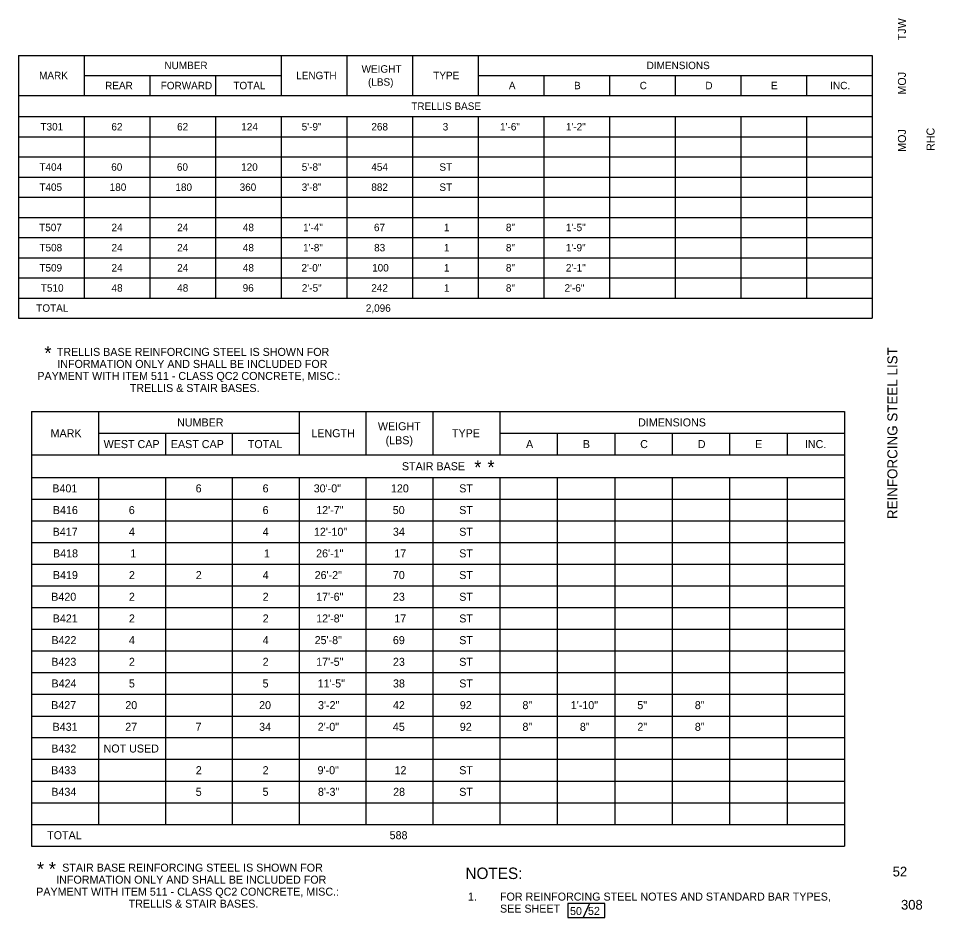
# Model space of a CAD drawing. Extents: x -47.5 to 51.5, y 0.9 to 23.7.
# Drawn here: x 17.38 to 33.41, y 0.94 to 16.66 of the extents above; entities that cross this region are included whole.
import ezdxf

# ---------------------------------------------------------------- set-up
doc = ezdxf.new("R2010")
doc.units = 0
for name, color, linetype in [('BR_P_Gen_Text', 7, 'Continuous'), ('BR_X_Slab_Const_Joint', 7, 'Continuous'), ('BR_X_Slab_Object', 7, 'Continuous')]:
    doc.layers.add(name, color=color, linetype=linetype)

msp = doc.modelspace()

# ---------------------------------------------------------------- linework, layer by layer
at = {"layer": 'BR_X_Slab_Const_Joint'}
msp.add_line((27.372, 1.195), (27.257, 0.945), dxfattribs=at)
msp.add_lwpolyline([(26.99, 0.945), (27.64, 0.945), (27.64, 1.195), (26.99, 1.195)], close=True, dxfattribs=at)
at = {"layer": 'BR_X_Slab_Object'}
for p, q in [((17.385, 16.015), (32.314, 16.015)), ((17.385, 16.015), (17.385, 11.422)), ((18.533, 16.015), (18.533, 15.311)), ((21.978, 16.015), (21.978, 15.311)), ((23.127, 16.015), (23.127, 15.311)), ((24.275, 16.015), (24.275, 15.311)), ((25.424, 16.015), (25.424, 15.311)), ((32.314, 16.015), (32.314, 11.422)), ((18.533, 15.663), (21.978, 15.663)), ((19.681, 15.663), (19.681, 15.311)), ((20.83, 15.663), (20.83, 15.311)), ((25.424, 15.663), (32.314, 15.663)), ((26.572, 15.663), (26.572, 15.311)), ((27.72, 15.663), (27.72, 15.311)), ((28.869, 15.663), (28.869, 15.311)), ((30.017, 15.663), (30.017, 15.311)), ((31.166, 15.663), (31.166, 15.311)), ((17.385, 15.311), (32.314, 15.311)), ((17.385, 14.944), (32.314, 14.944)), ((18.533, 14.944), (18.533, 11.774)), ((19.681, 14.944), (19.681, 11.774)), ((20.83, 14.944), (20.83, 11.774)), ((21.978, 14.944), (21.978, 11.774)), ((23.127, 14.944), (23.127, 11.774)), ((24.275, 14.944), (24.275, 11.774)), ((25.424, 14.944), (25.424, 11.774)), ((26.572, 14.944), (26.572, 11.774)), ((27.72, 14.944), (27.72, 11.774)), ((28.869, 14.944), (28.869, 11.774)), ((30.017, 14.944), (30.017, 11.774)), ((31.166, 14.944), (31.166, 11.774)), ((17.385, 14.591), (32.314, 14.591)), ((17.385, 14.239), (32.314, 14.239)), ((17.385, 13.887), (32.314, 13.887)), ((17.385, 13.535), (32.314, 13.535)), ((17.385, 13.183), (32.314, 13.183)), ((17.385, 12.831), (32.314, 12.831)), ((17.385, 12.478), (32.314, 12.478)), ((17.385, 12.126), (32.314, 12.126)), ((17.385, 11.774), (32.314, 11.774)), ((17.385, 11.422), (32.314, 11.422)), ((17.616, 9.789), (31.83, 9.789)), ((17.616, 9.789), (17.616, 2.196)), ((18.785, 9.789), (18.785, 9.032)), ((22.294, 9.789), (22.294, 9.032)), ((23.463, 9.789), (23.463, 9.032)), ((24.632, 9.789), (24.632, 9.032)), ((25.802, 9.789), (25.802, 9.032)), ((31.83, 9.789), (31.83, 2.196)), ((18.785, 9.411), (22.294, 9.411)), ((19.955, 9.411), (19.955, 9.032)), ((21.124, 9.411), (21.124, 9.032)), ((25.802, 9.411), (31.83, 9.411)), ((26.806, 9.411), (26.806, 9.032)), ((27.811, 9.411), (27.811, 9.032)), ((28.816, 9.411), (28.816, 9.032)), ((29.821, 9.411), (29.821, 9.032)), ((30.825, 9.411), (30.825, 9.032)), ((17.616, 9.032), (31.83, 9.032)), ((17.616, 8.636), (31.83, 8.636)), ((18.785, 8.636), (18.785, 2.575)), ((19.955, 8.636), (19.955, 2.575)), ((21.124, 8.636), (21.124, 2.575)), ((22.294, 8.636), (22.294, 2.575)), ((23.463, 8.636), (23.463, 2.575)), ((24.632, 8.636), (24.632, 2.575)), ((25.802, 8.636), (25.802, 2.575)), ((26.806, 8.636), (26.806, 2.575)), ((27.811, 8.636), (27.811, 2.575)), ((28.816, 8.636), (28.816, 2.575)), ((29.821, 8.636), (29.821, 2.575)), ((30.825, 8.636), (30.825, 2.575)), ((17.616, 8.258), (31.83, 8.258)), ((17.616, 7.879), (31.83, 7.879)), ((17.616, 7.5), (31.83, 7.5)), ((17.616, 7.121), (31.83, 7.121)), ((17.616, 6.742), (31.83, 6.742)), ((17.616, 6.364), (31.83, 6.364)), ((17.616, 5.985), (31.83, 5.985)), ((17.616, 5.606), (31.83, 5.606)), ((17.616, 5.227), (31.83, 5.227)), ((17.616, 4.848), (31.83, 4.848)), ((17.616, 4.469), (31.83, 4.469)), ((17.616, 4.091), (31.83, 4.091)), ((17.616, 3.712), (31.83, 3.712)), ((17.616, 3.333), (31.83, 3.333)), ((17.616, 2.954), (31.83, 2.954)), ((17.616, 2.575), (31.83, 2.575)), ((17.616, 2.196), (31.83, 2.196))]:
    msp.add_line(p, q, dxfattribs=at)

# ---------------------------------------------------------------- texts
at = {"layer": 'BR_P_Gen_Text'}
for s, height, p in [('NUMBER', 0.1302, (19.939, 15.774)), ('DIMENSIONS', 0.1302, (28.37, 15.774)), ('MARK', 0.1302, (17.748, 15.598)), ('LENGTH', 0.1302, (22.243, 15.598)), ('WEIGHT', 0.1302, (23.386, 15.712)), ('TYPE', 0.1302, (24.639, 15.598)), ('REAR', 0.1302, (18.902, 15.422)), ('FORWARD', 0.1302, (19.874, 15.422)), ('TOTAL', 0.1302, (21.144, 15.422)), ('(LBS)', 0.1302, (23.498, 15.484)), ('A', 0.13, (25.961, 15.422)), ('B', 0.13, (27.101, 15.422)), ('C', 0.13, (28.248, 15.422)), ('D', 0.13, (29.397, 15.422)), ('E', 0.13, (30.544, 15.422)), ('INC.', 0.1302, (31.579, 15.422)), ('TRELLIS BASE', 0.13015, (24.255, 15.062)), ('T301', 0.1302, (17.772, 14.702)), ('62', 0.1302, (19.012, 14.702)), ('62', 0.1302, (20.16, 14.702)), ('124', 0.1302, (21.283, 14.702)), ('5\'-9"', 0.1302, (22.339, 14.702)), ('268', 0.1302, (23.557, 14.702)), ('3', 0.13, (24.804, 14.702)), ('1\'-6"', 0.1302, (25.807, 14.702)), ('1\'-2"', 0.1302, (26.958, 14.702)), ('T404', 0.1302, (17.753, 13.998)), ('60', 0.1302, (19.009, 13.998)), ('60', 0.1302, (20.157, 13.998)), ('120', 0.1302, (21.28, 13.998)), ('5\'-8"', 0.1302, (22.34, 13.998)), ('454', 0.1302, (23.556, 13.998)), ('ST', 0.1302, (24.746, 13.998)), ('T405', 0.1302, (17.752, 13.646)), ('180', 0.1302, (18.982, 13.646)), ('180', 0.1302, (20.131, 13.646)), ('360', 0.1302, (21.254, 13.646)), ('3\'-8"', 0.1302, (22.339, 13.646)), ('882', 0.1302, (23.556, 13.646)), ('ST', 0.1302, (24.746, 13.646)), ('T507', 0.1302, (17.749, 12.942)), ('24', 0.1302, (19.014, 12.942)), ('24', 0.1302, (20.162, 12.942)), ('48', 0.1302, (21.31, 12.942)), ('1\'-4"', 0.1302, (22.363, 12.942)), ('67', 0.1302, (23.602, 12.942)), ('1', 0.13, (24.825, 12.942)), ('8"', 0.1302, (25.909, 12.942)), ('1\'-5"', 0.1302, (26.957, 12.942)), ('T508', 0.1302, (17.754, 12.589)), ('24', 0.1302, (19.014, 12.589)), ('24', 0.1302, (20.162, 12.589)), ('48', 0.1302, (21.31, 12.589)), ('1\'-8"', 0.1302, (22.363, 12.589)), ('83', 0.1302, (23.605, 12.589)), ('1', 0.13, (24.825, 12.589)), ('8"', 0.1302, (25.909, 12.589)), ('1\'-9"', 0.1302, (26.956, 12.589)), ('T509', 0.1302, (17.753, 12.237)), ('24', 0.1302, (19.014, 12.237)), ('24', 0.1302, (20.162, 12.237)), ('48', 0.1302, (21.31, 12.237)), ('2\'-0"', 0.1302, (22.335, 12.237)), ('100', 0.1302, (23.57, 12.237)), ('1', 0.13, (24.825, 12.237)), ('8"', 0.1302, (25.909, 12.237)), ('2\'-1"', 0.1302, (26.958, 12.237)), ('T510', 0.1302, (17.779, 11.885)), ('48', 0.1302, (19.014, 11.885)), ('48', 0.1302, (20.162, 11.885)), ('96', 0.1302, (21.307, 11.885)), ('2\'-5"', 0.1302, (22.341, 11.885)), ('242', 0.1302, (23.556, 11.885)), ('8"', 0.1302, (25.909, 11.885)), ('2\'-6"', 0.1302, (26.934, 11.885)), ('1', 0.13, (24.825, 11.885)), ('TOTAL', 0.1302, (17.698, 11.533)), ('2,096', 0.1302, (23.46, 11.533)), ('NUMBER', 0.14, (20.161, 9.53)), ('DIMENSIONS', 0.14, (28.22, 9.53)), ('MARK', 0.14, (17.949, 9.341)), ('LENGTH', 0.14, (22.508, 9.341)), ('WEIGHT', 0.14, (23.671, 9.463)), ('TYPE', 0.14, (24.966, 9.341)), ('WEST CAP', 0.14, (18.876, 9.151)), ('EAST CAP', 0.14, (20.051, 9.151)), ('TOTAL', 0.14, (21.397, 9.151)), ('(LBS)', 0.14, (23.806, 9.218)), ('C', 0.14, (28.257, 9.151)), ('INC.', 0.14, (31.136, 9.151)), ('A', 0.14, (26.261, 9.151)), ('B', 0.14, (27.254, 9.151)), ('D', 0.14, (29.264, 9.151)), ('E', 0.14, (30.266, 9.151)), ('STAIR BASE ', 0.14, (24.091, 8.764)), ('B401', 0.14, (17.979, 8.377)), ('6', 0.14, (20.485, 8.377)), ('6', 0.14, (21.655, 8.377)), ('30\'-0"', 0.14, (22.549, 8.377)), ('120', 0.14, (23.899, 8.377)), ('ST', 0.14, (25.093, 8.377)), ('B416', 0.14, (17.988, 7.998)), ('6', 0.14, (19.316, 7.998)), ('6', 0.14, (21.655, 7.998)), ('12\'-7"', 0.14, (22.593, 7.998)), ('50', 0.14, (23.931, 7.998)), ('ST', 0.14, (25.093, 7.998)), ('B417', 0.14, (17.985, 7.619)), ('4', 0.14, (19.318, 7.619)), ('4', 0.14, (21.657, 7.619)), ('12\'-10"', 0.14, (22.553, 7.619)), ('34', 0.14, (23.934, 7.619)), ('ST', 0.14, (25.093, 7.619)), ('B418', 0.14, (17.991, 7.241)), ('1', 0.14, (19.341, 7.241)), ('1', 0.14, (21.68, 7.241)), ('26\'-1"', 0.14, (22.591, 7.241)), ('17', 0.14, (23.958, 7.241)), ('ST', 0.14, (25.093, 7.241)), ('B419', 0.14, (17.989, 6.862)), ('2', 0.14, (19.318, 6.862)), ('2', 0.14, (20.487, 6.862)), ('4', 0.14, (21.657, 6.862)), ('26\'-2"', 0.14, (22.565, 6.862)), ('70', 0.14, (23.932, 6.862)), ('ST', 0.14, (25.093, 6.862)), ('B420', 0.14, (17.96, 6.483)), ('2', 0.14, (19.318, 6.483)), ('2', 0.14, (21.656, 6.483)), ('17\'-6"', 0.14, (22.591, 6.483)), ('23', 0.14, (23.934, 6.483)), ('ST', 0.14, (25.093, 6.483)), ('B421', 0.14, (17.986, 6.104)), ('2', 0.14, (19.318, 6.104)), ('2', 0.14, (21.656, 6.104)), ('12\'-8"', 0.14, (22.592, 6.104)), ('17', 0.14, (23.958, 6.104)), ('ST', 0.14, (25.093, 6.104)), ('B422', 0.14, (17.963, 5.725)), ('4', 0.14, (19.318, 5.725)), ('4', 0.14, (21.657, 5.725)), ('25\'-8"', 0.14, (22.565, 5.725)), ('69', 0.14, (23.933, 5.725)), ('ST', 0.14, (25.093, 5.725)), ('B423', 0.14, (17.961, 5.346)), ('2', 0.14, (19.318, 5.346)), ('2', 0.14, (21.656, 5.346)), ('17\'-5"', 0.14, (22.592, 5.346)), ('23', 0.14, (23.934, 5.346)), ('ST', 0.14, (25.093, 5.346)), ('B424', 0.14, (17.964, 4.968)), ('5', 0.14, (19.317, 4.968)), ('5', 0.14, (21.655, 4.968)), ('11\'-5"', 0.14, (22.619, 4.968)), ('38', 0.14, (23.935, 4.968)), ('ST', 0.14, (25.093, 4.968)), ('B427', 0.14, (17.959, 4.589)), ('20', 0.14, (19.255, 4.589)), ('20', 0.14, (21.594, 4.589)), ('3\'-2"', 0.14, (22.624, 4.589)), ('42', 0.14, (23.934, 4.589)), ('92', 0.14, (25.103, 4.589)), ('8"', 0.14, (26.198, 4.589)), ('1\'-10"', 0.14, (27.043, 4.589)), ('5"', 0.14, (28.207, 4.589)), ('8"', 0.14, (29.212, 4.589)), ('B431', 0.14, (17.984, 4.21)), ('27', 0.14, (19.254, 4.21)), ('7', 0.14, (20.483, 4.21)), ('34', 0.14, (21.595, 4.21)), ('2\'-0"', 0.14, (22.619, 4.21)), ('45', 0.14, (23.933, 4.21)), ('92', 0.14, (25.103, 4.21)), ('8"', 0.14, (26.198, 4.21)), ('8"', 0.14, (27.202, 4.21)), ('2"', 0.14, (28.208, 4.21)), ('8"', 0.14, (29.212, 4.21)), ('B432', 0.14, (17.961, 3.831)), ('NOT USED', 0.14, (18.875, 3.831)), ('B433', 0.14, (17.959, 3.452)), ('2', 0.14, (20.487, 3.452)), ('2', 0.14, (21.656, 3.452)), ('9\'-0"', 0.14, (22.616, 3.452)), ('12', 0.14, (23.962, 3.452)), ('ST', 0.14, (25.093, 3.452)), ('B434', 0.14, (17.961, 3.074)), ('5', 0.14, (20.486, 3.074)), ('5', 0.14, (21.655, 3.074)), ('8\'-3"', 0.14, (22.623, 3.074)), ('28', 0.14, (23.937, 3.074)), ('ST', 0.14, (25.093, 3.074)), ('TOTAL', 0.14, (17.889, 2.316)), ('588', 0.14, (23.876, 2.316)), ('52', 0.17, (32.671, 1.665)), ('50', 0.14, (27.03, 0.991)), ('52', 0.14, (27.344, 0.993)), ('308', 0.17, (32.817, 1.085))]:
    msp.add_text(s, height=height, dxfattribs=at).set_placement(p)
at = {"layer": 'BR_X_Slab_Const_Joint'}
for s, height, p in [('*', 0.24, (17.84, 10.692)), ('TRELLIS BASE REINFORCING STEEL IS SHOWN FOR', 0.14, (18.057, 10.762)), ('INFORMATION ONLY AND SHALL BE INCLUDED FOR ', 0.14, (18.066, 10.552)), ('PAYMENT WITH ITEM 511 - CLASS QC2 CONCRETE, MISC.:', 0.14, (17.717, 10.342)), ('TRELLIS & STAIR BASES.', 0.14, (19.333, 10.132)), ('*', 0.24, (25.355, 8.696)), ('*', 0.24, (25.586, 8.696)), ('*', 0.24, (17.71, 1.676)), ('*', 0.24, (17.917, 1.676)), ('STAIR BASE REINFORCING STEEL IS SHOWN FOR ', 0.14, (18.152, 1.749)), ('NOTES:', 0.2, (25.202, 1.62)), ('INFORMATION ONLY AND SHALL BE INCLUDED FOR ', 0.14, (18.047, 1.539)), ('PAYMENT WITH ITEM 511 - CLASS QC2 CONCRETE, MISC.:', 0.14, (17.697, 1.329)), ('1.', 0.14, (25.246, 1.243)), ('1.', 0.14, (25.246, 1.243)), ('FOR REINFORCING STEEL NOTES AND STANDARD BAR TYPES, ', 0.14, (25.806, 1.243)), ('FOR REINFORCING STEEL NOTES AND STANDARD BAR TYPES, ', 0.14, (25.806, 1.243)), ('TRELLIS & STAIR BASES.', 0.14, (19.313, 1.119)), ('SEE SHEET        .', 0.14, (25.806, 1.033)), ('SEE SHEET        .', 0.14, (25.806, 1.033))]:
    msp.add_text(s, height=height, dxfattribs=at).set_placement(p)
at = {"layer": 'BR_X_Slab_Object'}
for s, height, p in [('TJW', 0.14, (32.903, 16.278)), ('MOJ', 0.14, (32.903, 15.329)), ('RHC', 0.14, (33.403, 14.344)), ('MOJ', 0.14, (32.903, 14.329)), ('REINFORCING STEEL LIST', 0.175, (32.754, 7.91))]:
    msp.add_text(s, height=height, rotation=90, dxfattribs=at).set_placement(p)

doc.saveas('drawing.dxf')
